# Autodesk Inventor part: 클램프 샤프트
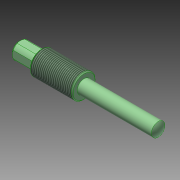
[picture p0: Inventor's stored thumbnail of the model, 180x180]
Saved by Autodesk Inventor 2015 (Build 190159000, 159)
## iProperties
Created: 2023-11
Part Number: 클램프 샤프트
Material: 강철, 탄소
Document SubType Name: Modeling
Designer: mdu-01
Density: 1 g/cm^3
Appearance: 기본값(1)
Author: mdu-01
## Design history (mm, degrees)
sketch "스케치1"
  geometry: L1 (0, 0)-(84, 0); L2 (0, 0)-(0, 4); L3 (1, 5)-(13, 5); L4 (13, 5)-(13, 7); L5 (13, 7)-(38, 7); L6 (38, 7)-(38, 4); L7 (38, 4)-(82.472, 4); L8 (0, 4)-(1, 5); A1 r 6 centre (78, 0) between (84, 0) and (82.472, 4); 1 further point
  constraints: 16 end point, 4 parallel, 3 point on line, 2 perpendicular, 2 point on circle, 1 centre point, 1 horizontal
  dimensions: "d0" = 6 radius of A1; "d2" = 8 diameter of L7 L1; "d3" = 14 diameter of L5 L1; "d4" = 10 diameter of L3 L1; "d5" = 13 distance between parallel lines of L4 L2; "d6" = 46 distance from line of L1.end L6; "d7" = 25 distance between parallel lines of L6 L4; "d8" = 1 distance of L2.end point (0, 5); "d9" = 1 distance of L3.start point (0, 5) (= d8)
revolve "회전1" sketch "스케치1" stored, may be unused: angle "d10" = 90 deg
feature "스레드1" dims "d11" = 10, "d12" = 0
chamfer "모따기1" distance "d13" = 0.541; stored, may be unused: second distance "d14" = 2, angle "d15" = 45 deg
sketch "스케치2"
  geometry: L1 (2.179, -4.5)-(-2.179, -4.5); L2 (-4.5, -2.179)-(-4.5, 2.179); L3 (-2.179, 4.5)-(2.179, 4.5); L4 (4.5, 2.179)-(4.5, -2.179); L5 (4.5, -4.5)-(-4.5, 4.5); L6 (-4.5, -4.5)-(4.5, 4.5); 2 further points
  constraints: 12 end point, 4 point on line, 2 horizontal alignment, 2 midpoint, 2 parallel, 2 vertical alignment, 1 horizontal, 1 perpendicular, 9 other
  dimensions: "d16" = 9 distance of L5.end L6.end; "d17" = 9 distance of L6.start L5.end
extrude "돌출1" cut sketch "스케치2" distance "d18" = 12; taper "d19" = 0 deg
sketch "스케치3"
  geometry: L1 (0, 0)-(-4.949, 0); L2 (-4.949, 0)-(-4.371, 1); L3 (-4.371, 1)-(-1.949, 1); L4 (-1.949, 1)-(0, 2.125); L5 (0, 2.125)-(0, 0)
  constraints: 10 end point, 1 horizontal, 1 parallel, 1 perpendicular
  dimensions: "d20" = 60 deg angle of L1 L2; "d21" = 2 diameter of L3 L1; "d23" = 3 horizontal distance of L3.end L1.end; "d24" = 30 deg angle of L1 L4; "d25" = 4.25 diameter of L4.end L1
revolve "회전2" sketch "스케치3" stored, may be unused: angle "d26" = 90 deg
node "솔리드1"
